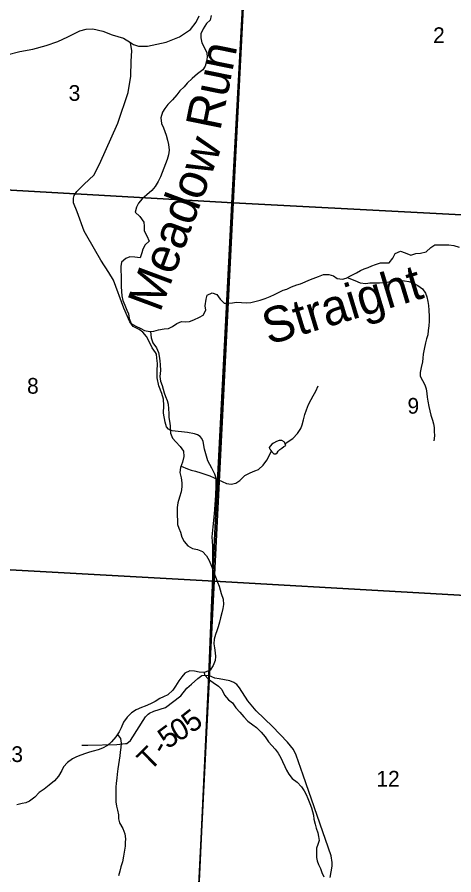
# Model space of a CAD drawing. Extents: x 0 to 34, y 0 to 22.
# Drawn here: x 25.404 to 26.568, y 14.481 to 16.768 of the extents above; entities that cross this region are included whole.
import ezdxf

# ---------------------------------------------------------------- set-up
doc = ezdxf.new("R2010")
doc.units = 0
for name, color, linetype in [('GM_X_County_Road', 7, 'Continuous'), ('GM_X_Minor_Lake', 7, 'Continuous'), ('GM_X_Minor_River', 7, 'Continuous'), ('GM_X_Minor_River_Text', 7, 'Continuous'), ('GM_X_Section', 7, 'Continuous'), ('GM_X_Section_Text', 7, 'Continuous'), ('GM_X_Township', 7, 'Continuous'), ('GM_X_Township_Road', 7, 'Continuous'), ('GM_X_Township_Road_Text', 7, 'Continuous')]:
    doc.layers.add(name, color=color, linetype=linetype)

msp = doc.modelspace()

# ---------------------------------------------------------------- linework, layer by layer
at = {"layer": 'GM_X_County_Road'}
for points in [[(25.1118, 16.5692), (25.327, 16.6512), (25.3767, 16.668), (25.4112, 16.6768), (25.4464, 16.6833), (25.4813, 16.6925), (25.5124, 16.7031), (25.5393, 16.7161), (25.5711, 16.7317), (25.5878, 16.7363), (25.6063, 16.7371), (25.6325, 16.7314), (25.6576, 16.7216), (25.6879, 16.7121), (25.7067, 16.7009), (25.7146, 16.6952), (25.7278, 16.6909), (25.7521, 16.6912), (25.8017, 16.7016), (25.8366, 16.7158), (25.8662, 16.7357), (25.8811, 16.7546), (25.8895, 16.7721)], [(25.9261, 15.2857), (25.9261, 15.2869), (25.9259, 15.3571), (25.924, 15.3818), (25.9271, 15.4089), (25.9299, 15.4431), (25.9336, 15.4926), (25.935, 15.5187), (25.935, 15.5382), (25.9313, 15.5493), (25.9233, 15.5651), (25.9124, 15.5845), (25.907, 15.6032), (25.9038, 15.6164), (25.9002, 15.6368), (25.8965, 15.6446), (25.8917, 15.65), (25.8851, 15.6541), (25.8768, 15.657), (25.8584, 15.6604), (25.8175, 15.665), (25.8073, 15.6694), (25.8027, 15.6757), (25.7988, 15.6877), (25.7947, 15.712), (25.795, 15.7324), (25.7942, 15.7495), (25.7895, 15.7644), (25.7822, 15.7853), (25.7775, 15.8061), (25.7771, 15.8245), (25.7784, 15.8449), (25.7763, 15.859), (25.7754, 15.8692), (25.7733, 15.8739), (25.7643, 15.8867), (25.756, 15.9029), (25.7492, 15.9162), (25.7391, 15.9283), (25.7298, 15.9348), (25.7132, 15.9433), (25.7048, 15.9554), (25.689, 15.9921), (25.6612, 16.0664), (25.6482, 16.087), (25.6273, 16.1201), (25.5902, 16.1849), (25.5826, 16.1971), (25.5638, 16.2488), (25.5547, 16.2735), (25.5543, 16.2853), (25.5563, 16.2923), (25.5634, 16.3029), (25.5831, 16.323), (25.6085, 16.3469), (25.6236, 16.3758), (25.6723, 16.4857), (25.6999, 16.5674), (25.7074, 16.6111), (25.7081, 16.651), (25.7096, 16.6787), (25.7067, 16.7009)], [(25.9162, 15.0319), (25.9233, 15.2144), (25.926, 15.2732), (25.9261, 15.2857)], [(26.2389, 14.4736), (26.2441, 14.5037), (26.2441, 14.5136), (26.2412, 14.5312), (26.1664, 14.7464), (26.1477, 14.7999), (26.1405, 14.8152), (26.1248, 14.8343), (26.0853, 14.8764), (26.0411, 14.918), (26.0192, 14.9443), (25.9972, 14.9797), (25.9896, 14.9883), (25.9818, 14.9936), (25.971, 14.9976), (25.9427, 15.0032), (25.931, 15.0052), (25.9155, 15.0123), (25.9162, 15.0319)]]:
    msp.add_lwpolyline(points, dxfattribs=at)
at = {"layer": 'GM_X_Minor_Lake'}
for points in [[(26.0805, 15.6128), (26.0834, 15.6092), (26.0882, 15.6035), (26.0935, 15.6034), (26.0977, 15.6063), (26.1001, 15.6108), (26.1047, 15.6153), (26.1101, 15.6186), (26.1155, 15.6227), (26.1201, 15.626), (26.119, 15.6306), (26.1157, 15.6359), (26.1101, 15.6387), (26.1029, 15.6388), (26.0953, 15.6367), (26.088, 15.6319), (26.083, 15.6293), (26.0761, 15.6208)], [(26.0761, 15.6208), (26.0771, 15.6171), (26.0784, 15.6156), (26.0805, 15.6128)]]:
    msp.add_lwpolyline(points, dxfattribs=at)
at = {"layer": 'GM_X_Minor_River'}
for points in [[(25.9211, 16.773), (25.919, 16.7601), (25.9094, 16.7512), (25.9, 16.737), (25.8941, 16.7238), (25.8943, 16.7132), (25.8966, 16.6999), (25.9036, 16.6861), (25.9102, 16.6734), (25.9111, 16.6613), (25.909, 16.6511), (25.9053, 16.6379), (25.8991, 16.6277), (25.8852, 16.617), (25.871, 16.6051), (25.8571, 16.5921), (25.8494, 16.5824), (25.8382, 16.572), (25.8297, 16.5612), (25.8185, 16.5481), (25.8061, 16.5354), (25.7976, 16.525), (25.7917, 16.5148), (25.7876, 16.4994), (25.7893, 16.4849), (25.794, 16.4731), (25.7976, 16.4635), (25.8011, 16.4532), (25.8054, 16.4402), (25.8075, 16.4284), (25.8095, 16.4136), (25.8081, 16.4015), (25.8041, 16.3883), (25.7953, 16.3657), (25.7909, 16.354), (25.7862, 16.3424), (25.7803, 16.3299), (25.7721, 16.3168), (25.7632, 16.3064), (25.7501, 16.2941), (25.7378, 16.2837), (25.7281, 16.2725), (25.7222, 16.2616), (25.7186, 16.2484), (25.7312, 16.2368), (25.7419, 16.2218), (25.7432, 16.2112), (25.7426, 16.1983), (25.7503, 16.1852), (25.7561, 16.1707), (25.7457, 16.1607), (25.739, 16.1498), (25.7366, 16.14), (25.7325, 16.126), (25.7178, 16.1282), (25.7042, 16.1292), (25.6935, 16.1249), (25.6823, 16.1148), (25.681, 16.1035), (25.6804, 16.0921), (25.6813, 16.0796), (25.6817, 16.0598), (25.6815, 16.05), (25.682, 16.0363), (25.6829, 16.0249), (25.6857, 16.0127), (25.6915, 16.0005), (25.697, 15.9871), (25.7009, 15.9768), (25.7026, 15.9646), (25.7084, 15.9508), (25.7207, 15.9442), (25.7339, 15.9382), (25.7436, 15.9324), (25.7583, 15.9298), (25.7689, 15.9307), (25.7807, 15.9343), (25.7963, 15.9371), (25.8077, 15.938), (25.818, 15.9431), (25.8303, 15.9512), (25.8425, 15.9563), (25.8534, 15.9557), (25.864, 15.9563), (25.8755, 15.9606), (25.8904, 15.9679), (25.9003, 15.973), (25.9074, 15.9869), (25.9057, 15.9987), (25.9079, 16.0161), (25.9104, 16.0271), (25.9238, 16.0333), (25.9366, 16.0285), (25.945, 16.0158), (25.9558, 16.0054), (25.9687, 16.0051), (25.9781, 16.0065), (25.9888, 16.0082)], [(25.9888, 16.0082), (26.0024, 16.0071), (26.0145, 16.0062), (26.0274, 16.0071), (26.0376, 16.0095), (26.0517, 16.0134), (26.0658, 16.0177), (26.0788, 16.0235), (26.0906, 16.0286), (26.1028, 16.0345), (26.1135, 16.0399), (26.123, 16.0432), (26.136, 16.049), (26.1497, 16.0541), (26.1593, 16.0569), (26.1719, 16.0627), (26.1822, 16.0671), (26.1936, 16.0711), (26.2077, 16.0765), (26.221, 16.0819), (26.2354, 16.082), (26.2475, 16.078), (26.2576, 16.0714), (26.2711, 16.0692), (26.281, 16.0724), (26.2944, 16.0794), (26.3089, 16.0867), (26.3193, 16.0922), (26.3292, 16.0966), (26.3395, 16.1006), (26.3494, 16.1049), (26.3597, 16.1089), (26.373, 16.1128), (26.3829, 16.1126), (26.3961, 16.1128), (26.4058, 16.1251), (26.4117, 16.1375), (26.4262, 16.1441), (26.439, 16.1396), (26.454, 16.1333), (26.4666, 16.138), (26.4791, 16.1389), (26.4947, 16.1424), (26.5066, 16.1543), (26.5174, 16.1609), (26.5299, 16.1614), (26.5446, 16.1608), (26.5548, 16.1614), (26.5681, 16.1592), (26.5823, 16.1544)], [(26.2836, 16.0738), (26.304, 16.0663), (26.3186, 16.0596), (26.3337, 16.0578), (26.3444, 16.0599), (26.3701, 16.0594), (26.3845, 16.061), (26.3948, 16.0623), (26.4054, 16.0637), (26.4156, 16.0657), (26.4255, 16.0663), (26.4372, 16.0653), (26.4481, 16.0629), (26.4605, 16.0584), (26.4722, 16.0525), (26.4845, 16.0436), (26.4926, 16.032), (26.4962, 16.0221), (26.4994, 16.0095), (26.5007, 15.9989), (26.5016, 15.9867), (26.5028, 15.97), (26.5029, 15.9575), (26.5019, 15.9454), (26.5002, 15.9325), (26.4988, 15.9208), (26.4956, 15.9099), (26.4924, 15.8993), (26.489, 15.883), (26.4865, 15.8691), (26.4859, 15.8588), (26.485, 15.8486), (26.4813, 15.8339), (26.4784, 15.8207), (26.4789, 15.8104), (26.4852, 15.7989), (26.491, 15.7878), (26.4942, 15.7767), (26.4962, 15.7646), (26.4976, 15.7547), (26.4993, 15.744), (26.5016, 15.7296), (26.5045, 15.7185), (26.5069, 15.7071), (26.5116, 15.6937), (26.5144, 15.6834), (26.5157, 15.6739), (26.5163, 15.6637), (26.5168, 15.6515), (26.5154, 15.6383)], [(25.7593, 15.9299), (25.7618, 15.9127), (25.7657, 15.8997), (25.7757, 15.8862), (25.7807, 15.8736), (25.7828, 15.8641), (25.7845, 15.8516), (25.7858, 15.8409), (25.7859, 15.8257), (25.7844, 15.8102), (25.7861, 15.7977), (25.7904, 15.7854), (25.7936, 15.7759), (25.7965, 15.7664), (25.8001, 15.7568), (25.804, 15.7454), (25.8065, 15.7358), (25.8083, 15.7108), (25.8089, 15.7009), (25.8106, 15.691), (25.8118, 15.6785), (25.8124, 15.669), (25.8134, 15.6591), (25.8184, 15.645), (25.8269, 15.6353), (25.8392, 15.6233), (25.848, 15.6103), (25.8485, 15.5966), (25.8452, 15.5811), (25.84, 15.5675), (25.8375, 15.5536), (25.841, 15.5395), (25.8434, 15.5261), (25.8436, 15.5151), (25.8418, 15.5019), (25.8366, 15.488), (25.8326, 15.4725), (25.8308, 15.4604), (25.831, 15.4486), (25.8312, 15.4387), (25.8317, 15.4255), (25.8318, 15.4152), (25.8354, 15.4049), (25.8394, 15.3946), (25.8433, 15.3816), (25.8491, 15.3694), (25.8588, 15.3578), (25.8715, 15.3507), (25.8851, 15.3486), (25.8979, 15.3434), (25.9094, 15.3318), (25.9159, 15.3188), (25.9225, 15.3043), (25.9257, 15.2947), (25.9297, 15.284), (25.9343, 15.271), (25.9379, 15.2611), (25.9423, 15.2504), (25.9455, 15.2409), (25.948, 15.2306), (25.9537, 15.2157), (25.9546, 15.202), (25.9525, 15.1907), (25.9496, 15.179), (25.9464, 15.1665), (25.9435, 15.1548), (25.9398, 15.142), (25.9366, 15.1314), (25.933, 15.1216), (25.929, 15.1092), (25.9288, 15.0967), (25.9301, 15.086), (25.9321, 15.0731), (25.9334, 15.0632), (25.9317, 15.0526), (25.9265, 15.0387), (25.9184, 15.0267), (25.9035, 15.0201), (25.8895, 15.0212), (25.8771, 15.0241), (25.8646, 15.025), (25.8508, 15.0181), (25.8431, 15.0084), (25.8353, 14.9979), (25.8263, 14.9837), (25.8193, 14.9728), (25.8058, 14.9605), (25.7944, 14.9551), (25.7848, 14.9511), (25.7722, 14.943), (25.7596, 14.9368), (25.7458, 14.9302), (25.7359, 14.927), (25.7218, 14.9208), (25.7092, 14.913), (25.6972, 14.9008), (25.6879, 14.8877), (25.6815, 14.8726), (25.676, 14.8617), (25.6671, 14.8486), (25.6555, 14.8355)], [(26.1185, 15.6315), (26.1393, 15.6446), (26.1517, 15.6576), (26.1607, 15.6711), (26.1643, 15.6809), (26.1679, 15.6938), (26.1712, 15.7081), (26.1752, 15.7213), (26.1812, 15.7352), (26.1879, 15.7484), (26.1933, 15.7585), (26.2004, 15.7709), (26.2063, 15.7848)], [(25.8412, 15.5706), (25.8581, 15.5638), (25.8683, 15.5598), (25.8799, 15.5569), (25.8943, 15.5532), (25.9074, 15.5488), (25.9176, 15.5452), (25.9296, 15.5393), (25.9393, 15.5353), (25.9506, 15.5298), (25.9622, 15.5247), (25.975, 15.5225), (25.9876, 15.5257), (25.9976, 15.5323), (26.0114, 15.5461), (26.0256, 15.5531), (26.0382, 15.5581), (26.0477, 15.5614), (26.06, 15.5729), (26.0694, 15.5864), (26.0823, 15.6107)], [(25.9028, 15.0202), (25.9037, 15.0141), (25.9141, 15.0021), (25.9268, 14.9939), (25.9406, 14.9842), (25.9499, 14.9745), (25.9568, 14.9596), (25.968, 14.9472), (25.978, 14.9391), (25.9876, 14.9264), (25.9976, 14.9148), (26.0084, 14.9021), (26.0191, 14.8901), (26.0325, 14.8804), (26.0422, 14.8734), (26.0549, 14.8614), (26.0652, 14.8483), (26.0741, 14.8352), (26.083, 14.8256), (26.0922, 14.8156), (26.1004, 14.8055), (26.1073, 14.7929), (26.1113, 14.7826), (26.1179, 14.7696), (26.1222, 14.7596), (26.1288, 14.7493), (26.1373, 14.7377), (26.1504, 14.7276), (26.1626, 14.7156), (26.1696, 14.7045), (26.1751, 14.6945), (26.1787, 14.6842), (26.1845, 14.6708), (26.1885, 14.6597), (26.1913, 14.6495), (26.1938, 14.6395), (26.1954, 14.6289), (26.1986, 14.6159), (26.2014, 14.6053), (26.2054, 14.5923), (26.2078, 14.5824), (26.2091, 14.5721), (26.2059, 14.5616), (26.2019, 14.5514), (26.2024, 14.5381), (26.2022, 14.5271), (26.2039, 14.5176), (26.2079, 14.5077), (26.2126, 14.497), (26.2162, 14.487), (26.2221, 14.4752)], [(25.6715, 14.855), (25.6795, 14.8442), (25.6812, 14.832), (25.6809, 14.8203), (25.6788, 14.8082), (25.6775, 14.798), (25.6761, 14.7866), (25.6744, 14.7749), (25.6723, 14.7635), (25.6705, 14.7488), (25.6695, 14.7382), (25.6685, 14.7253), (25.6676, 14.7147), (25.6669, 14.6992), (25.6671, 14.6878), (25.6676, 14.6756), (25.6689, 14.6635), (25.6717, 14.6528), (25.6741, 14.6406), (25.6747, 14.63), (25.6771, 14.6197), (25.6863, 14.604), (25.6913, 14.5895), (25.6926, 14.5762), (25.6924, 14.5667), (25.6919, 14.5568), (25.6893, 14.5406), (25.6876, 14.5304), (25.6846, 14.5149), (25.6806, 14.502), (25.6777, 14.4907), (25.6741, 14.4779)], [(25.6555, 14.8355), (25.6447, 14.8251), (25.6317, 14.8182), (25.6206, 14.8142), (25.607, 14.8107), (25.5967, 14.8082), (25.5868, 14.8046), (25.5738, 14.7999), (25.562, 14.7956), (25.5513, 14.7901), (25.5383, 14.7805), (25.5274, 14.7689), (25.5231, 14.7591), (25.5141, 14.7441), (25.5036, 14.7311), (25.4898, 14.7199), (25.4764, 14.7088), (25.4626, 14.7), (25.451, 14.6877), (25.4375, 14.6769), (25.4272, 14.6726), (25.4177, 14.6705), (25.4037, 14.6677)]]:
    msp.add_lwpolyline(points, dxfattribs=at)
at = {"layer": 'GM_X_Section'}
for points in [[(26.2538, 17.2713), (27.0604, 17.2208), (27.0998, 17.2184), (27.0114, 16.2186), (25.9802, 16.2732), (26.0152, 16.9679), (26.1318, 17.0242)], [(25.9802, 16.2732), (25.9296, 15.2643), (24.9048, 15.3211), (24.9665, 16.3307)], [(27.0114, 16.2186), (26.9263, 15.2069), (25.9296, 15.2643), (25.9802, 16.2732)], [(25.9296, 15.2643), (25.8818, 14.3145), (24.8423, 14.3642), (24.9048, 15.3211)], [(26.9263, 15.2069), (26.8411, 14.2004), (25.8818, 14.3145), (25.9296, 15.2643)]]:
    msp.add_lwpolyline(points, close=True, dxfattribs=at)
msp.add_lwpolyline([(26.0152, 16.9679), (25.9802, 16.2732), (24.9665, 16.3307), (24.9804, 16.5448), (25.0031, 16.5575), (25.0207, 16.5664), (25.0339, 16.5765), (25.0442, 16.5841), (25.0586, 16.5954), (25.0754, 16.6093), (25.0929, 16.624), (25.1077, 16.6391), (25.1187, 16.6489), (25.1332, 16.6594), (25.1488, 16.6722), (25.1617, 16.6854), (25.1762, 16.6978), (25.1883, 16.708), (25.1978, 16.7163), (25.2169, 16.7348), (25.223, 16.7404), (25.237, 16.7517), (25.2583, 16.7675), (25.2762, 16.7807)], dxfattribs=at)
at = {"layer": 'GM_X_Township'}
for points in [[(25.8726, 14.1), (25.8823, 14.3113), (25.9155, 15.0123), (25.9233, 15.2144), (25.926, 15.2732), (25.9261, 15.2869), (25.9768, 16.2716), (26.0061, 16.8119)], [(26.0061, 16.8119), (25.9768, 16.2716), (25.9261, 15.2869), (25.926, 15.2732), (25.9233, 15.2144), (25.9155, 15.0123), (25.8823, 14.3113), (26.1128, 14.2885), (27.704, 14.1)]]:
    msp.add_lwpolyline(points, dxfattribs=at)
at = {"layer": 'GM_X_Township_Road'}
msp.add_lwpolyline([(25.5768, 14.8263), (25.5927, 14.8264), (25.6698, 14.8284), (25.6932, 14.8305), (25.6967, 14.8312), (25.7062, 14.8392), (25.7464, 14.9022), (25.7531, 14.9092), (25.7566, 14.912), (25.7685, 14.9173), (25.7993, 14.9267), (25.8409, 14.9582), (25.8568, 14.9786), (25.8692, 14.9895), (25.8858, 15.0047), (25.8964, 15.012), (25.9038, 15.0128), (25.9155, 15.0123)], dxfattribs=at)

# ---------------------------------------------------------------- texts
at = {"layer": 'GM_X_Minor_River_Text'}
for s, height, rotation, p in [('Run', 0.09471, 78.4995, (25.9454, 16.4629)), ('Meadow', 0.09471, 69.5661, (25.785, 15.9784)), ('Straight', 0.09469, 16.8792, (26.0747, 15.8936))]:
    msp.add_text(s, height=height, rotation=rotation, dxfattribs=at).set_placement(p)
at = {"layer": 'GM_X_Section_Text'}
for s, height, p in [('2', 0.0419, (26.513, 16.6993)), ('3', 0.0419, (25.5414, 16.5452)), ('8', 0.0419, (25.4306, 15.764)), ('9', 0.0419, (26.4447, 15.7107)), ('13', 0.04186, (25.3576, 14.7815)), ('12', 0.04186, (26.3618, 14.716))]:
    msp.add_text(s, height=height, rotation=0, dxfattribs=at).set_placement(p)
at = {"layer": 'GM_X_Township_Road_Text'}
for s, rotation, p in [('5', 38.0179, (25.8703, 14.8565)), ('0', 29.9275, (25.8327, 14.8341)), ('5', 36.7471, (25.8062, 14.8142)), ('T', 44.7667, (25.7583, 14.7554)), ('-', 60.1729, (25.7986, 14.7985))]:
    msp.add_text(s, height=0.0568, rotation=rotation, dxfattribs=at).set_placement(p)

doc.saveas('drawing.dxf')
